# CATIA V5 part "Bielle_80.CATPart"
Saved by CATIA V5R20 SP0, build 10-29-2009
Part number: Manivelle
Bounding box of the stored display mesh (mm): x -20 to 20, y -55 to 55, z -15 to 15
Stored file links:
  D:\thinkmotion-MPB\Dropbox\IAO_2011\MMS_GR3\aweinling\aweinling\Bielle_80.CATPart
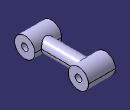
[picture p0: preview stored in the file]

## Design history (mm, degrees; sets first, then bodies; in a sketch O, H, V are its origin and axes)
Parameters
  `Longueur L` = 80 mm
  D_Trou = 10 mm
  D_Pivot = 30 mm
  D_Bielle = 20 mm
  `Largeur La` = 40 mm
Body1 (main body)
  Sketch1 on yz-plane, origin (0, 0, 0), H (0, 1, 0), V (0, 0, 1)
    circle A1 centre (40, 0) radius 15
    point P1 (40, 0)
    point P2 (-40, 0)
    circle A2 centre (-40, 0) radius 15
    radius A1 = 15 {= D_Pivot  /2}
    distance P2 P1 = 80 {= `Longueur L`}
    coincidence: P1 H
    symmetry: A1 A2 V
  Pad1: profile Sketch1, direction (1, 0, 0), length 20 {= `Largeur La` /2}, mirrored extent
  Sketch2 on zx-plane, origin (0, 0, 0), H (-1, 0, 0), V (0, 0, 1)
    circle A1 centre (0, 0) radius 10
    point P1 (10, 0)
    radius A1 = 10 {= D_Bielle /2}
    coincidence: P1 A1, P1 H
  Pad2: profile Sketch2, direction (0, 1, 0), length 40 {= `Longueur L` /2}, mirrored extent
  Sketch3 on end face of Pad1, origin (20, 96.2753, 0), H (0, 1, 0), V (0, 0, 1)
    point P1 (-56.2753, 0)
    reference projected circle E1 centre (-56.2753, 0) radius 15 from edge [face of Pad1 from Sketch1.A1 | end face of Pad1]
    concentricity: P1 E1
  Hole1: placed by Sketch3, at (20, 40, 0) direction (-1, 0, 0), diameter 10 {= D_Trou}, through (limit type 6)
  RectPattern1: of Hole1, direction 1 instances 2, spacing 80 {= `Longueur L`}, along axis of face of Pad2 from Sketch2.A1 reversed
